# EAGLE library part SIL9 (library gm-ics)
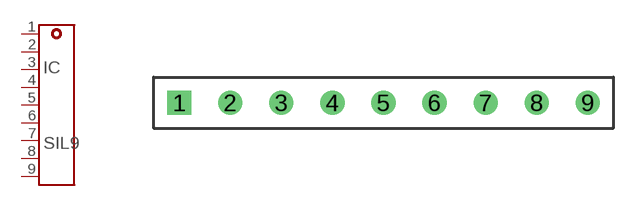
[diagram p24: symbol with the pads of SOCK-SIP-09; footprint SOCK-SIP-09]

Designator prefix IC

## SIL9  [SOCK-SIP-09]
1  1  pas
2  2  pas
3  3  pas
4  4  pas
5  5  pas
6  6  pas
7  7  pas
8  8  pas
9  9  pas

## Footprint SOCK-SIP-09 (pad centres in mm)
drill 0.7 square: 1 -10.16,0
drill 0.7 round: 2 -7.62,0; 3 -5.08,0; 4 -2.54,0; 5 0,0; 6 2.54,0; 7 5.08,0; 8 7.62,0; 9 10.16,0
